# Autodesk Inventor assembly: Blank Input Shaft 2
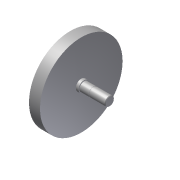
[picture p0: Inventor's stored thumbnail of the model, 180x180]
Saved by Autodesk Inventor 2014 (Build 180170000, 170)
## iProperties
Created: 2011-01
Part Number: Blank Input Shaft 2
Document SubType Name: Assembly
Designer: Beta-8540w
ClientObjectVersion: 1
Author: Beta-8540w
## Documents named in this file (2)
- C:\Inventor 2014 Essentials\Assemblies\Chapter 09\Design Accelerators\Blank Input Shaft 2.iam
- C:\Inventor 2014 Essentials\Assemblies\Chapter 09\Design Accelerators\Blank Input Shaft 2.ipt
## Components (1 placed, 1 different names)
1. Blank Input Shaft 2:1
